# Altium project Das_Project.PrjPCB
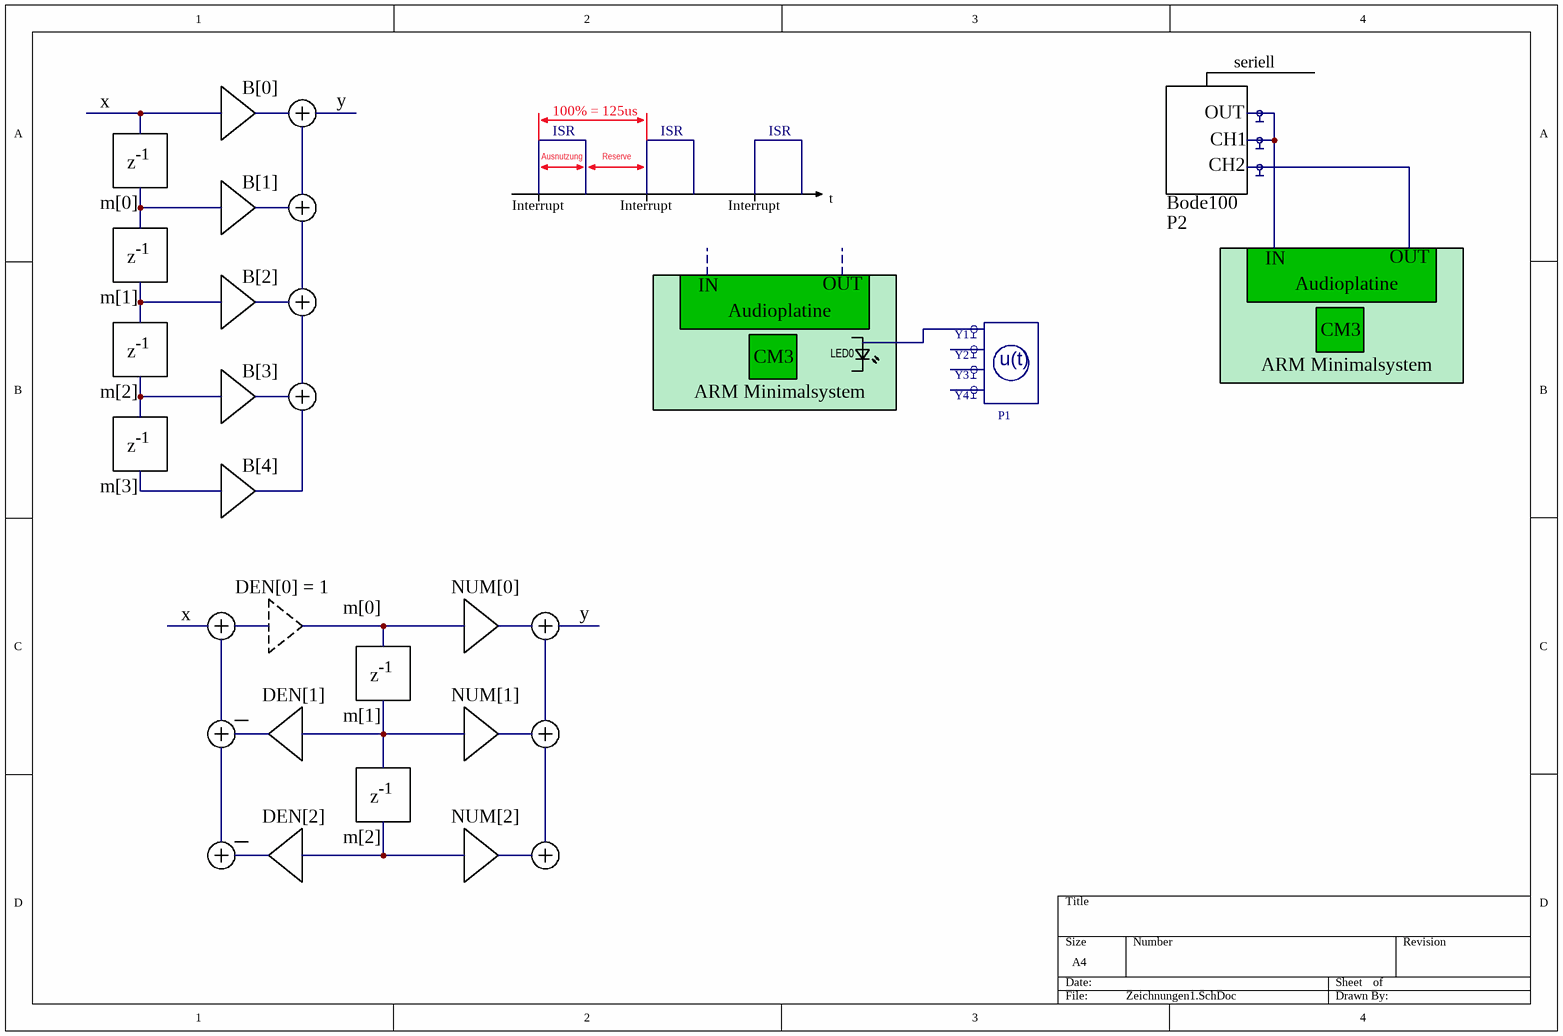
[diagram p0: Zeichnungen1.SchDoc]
1 sheet, 1 parts. Net scope: global (net labels, ports and power ports of the same name join across sheets).

## Sheet Zeichnungen1.SchDoc
size A4; PageSetup: Record=PageOptions¦CenterHorizontal=True¦CenterVertical=True¦PrintScale=1.00¦XCorrection=1.00¦YCorrection=1.00¦PrintKind=0¦BorderSize=5000000¦LeftOffset=0¦BottomOffset=0¦Orientation=2¦PaperLength=1000¦PaperWidth=1000¦Scale=100¦PaperSource=7¦PrintQuality=-3¦MediaType=1¦DitherType=10¦PrintScaleMode=1¦PaperKind=A4¦PaperIndex=9

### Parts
P1  Oszilloskop4Kanal  (value not drawn)

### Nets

Not connected (* = marked no-connect by the designer): P1 1 2 3 4

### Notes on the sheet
- x
- B[0]
- y
- 100% = 125us
- seriell
- z
- -1
- Ausnutzung
- ISR
- Reserve
- OUT
- CH2
- CH1
- m[0]
- B[1]
- Interrupt
- t
- Bode100
- P2
- m[1]
- B[2]
- IN
- Audioplatine
- B[3]
- CM3
- LED0
- ARM Minimalsystem
- m[2]
- m[3]
- B[4]
- DEN[0] = 1
- NUM[0]
- DEN[1]
- NUM[1]
- DEN[2]
- NUM[2]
